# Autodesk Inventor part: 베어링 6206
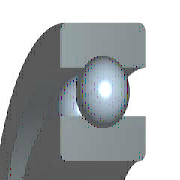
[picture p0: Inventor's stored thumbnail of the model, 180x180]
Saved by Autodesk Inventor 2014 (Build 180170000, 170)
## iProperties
Created: 2009-02
Part Number: 베어링 6206
Material: Steel, Mild
Description: 깊은 그루브 볼 베어링
Document SubType Name: Modeling
Standard: KS B 2023
Designer: KYOUNG IL JANG
Standards Organization: KS
Language: ko-KR
Size Designation: 6206 - 30 x 62 x 16
Categories: <MemberInstance><Categories><Category DisplayName="샤프트 부품" InternalName="7f7aeb1f-a693-4053-b835-cee3144e0d98" Mnemonic="SHFT"><Category DisplayName="베어링" Inter
Density: 1 g/cm^3
Appearance: Metal-Steel
Company: 한국ATC센터
IsCustomPart: 0
Author: KYOUNG IL JANG
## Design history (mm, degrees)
sketch "스케치" dims "d0" = 8.32 (= -0.26 x WD + 0.26 x BD)
  geometry: L1 (3.84, 23)-(12.16, 23); L2 (8, 23)-(8, 18.84); L3 (8, 23)-(8, 27.16); L4 (4.909, 20.216)-(0, 20.216); L5 (0, 15)-(16, 15); L6 (4.909, 25.784)-(0, 25.784); L7 (0, 31)-(16, 31); L8 (16, 15)-(16, 20.216); L9 (11.091, 20.216)-(16, 20.216); L10 (11.091, 25.784)-(16, 25.784); L11 (16, 31)-(16, 25.784); L12 (-1.4, 0)-(8.4, 0) reference; L13 (0, -0.3)-(0, 5.3) reference
  constraints: 22 end point, 4 point on line, 2 collinear, 2 perpendicular, 2 symmetric about line, 1 midpoint, 1 parallel, 14 other
  dimensions: "d9" = 30 diameter of L5 L12 (= WD); "d11" = 62 diameter of L7 L12 (= BD); "d12" = 16 distance between parallel lines of L8 L13 (= KB); "d13" = 40.432 diameter of L9 L12 (= 0.326 x BD + 0.674 x WD)
revolve "본체" stored, may be unused: angle "d6" = 90 deg
revolve "볼" stored, may be unused: angle "d7" = 90 deg
pattern_circular "IDS_ARRAYBALL[SIMPL:T]" dims angle "d3" = 360 deg
body "Solid1"
fillet "모깎기1" dims "d1" = 1 (= KRS)
other parameters: "WD" = 30 [user parameter; used in 5 equation terms], "BD" = 62 [user parameter; used in 5 equation terms], "KB" = 16 [user parameter; used in 1 equation term], "KRS" = 1 [user parameter; used in 1 equation term], "d4" = 0, "d5" = 0, "d8" = 0, "d14" = 0, "d15" = 0, "BBA" = 0 [user parameter], "BC0" = 1.12e+07 [user parameter], "BC" = 1.95e+07 [user parameter], "BR" = 31 (= 0.5 x BD) [user parameter], "WR" = 15 (= 0.5 x WD) [user parameter]
